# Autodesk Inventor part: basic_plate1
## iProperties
Created: 2005-10
Part Number: basic_plate1
Document SubType Name: Modeling
Designer: hassen
Density: 1 g/cm^3
Author: hassen
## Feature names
1. Extrusion1
2. Extrusion2
3. Hole1
4. Extrusion3
5. Sweep3
6. Fillet2
7. Fillet3
8. Fillet4
9. Circular Pattern1
10. Fillet5
11. Fillet6
12. Chamfer1
13. Hole2
